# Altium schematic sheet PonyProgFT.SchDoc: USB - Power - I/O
size A3; Author: Claudio Lanconelli; CompanyName: Eurek srl; DrawnBy: Claudio Lanconelli; Organization: Eurek srl; DocumentNumber: 1; SheetNumber: 1; SheetTotal: 1
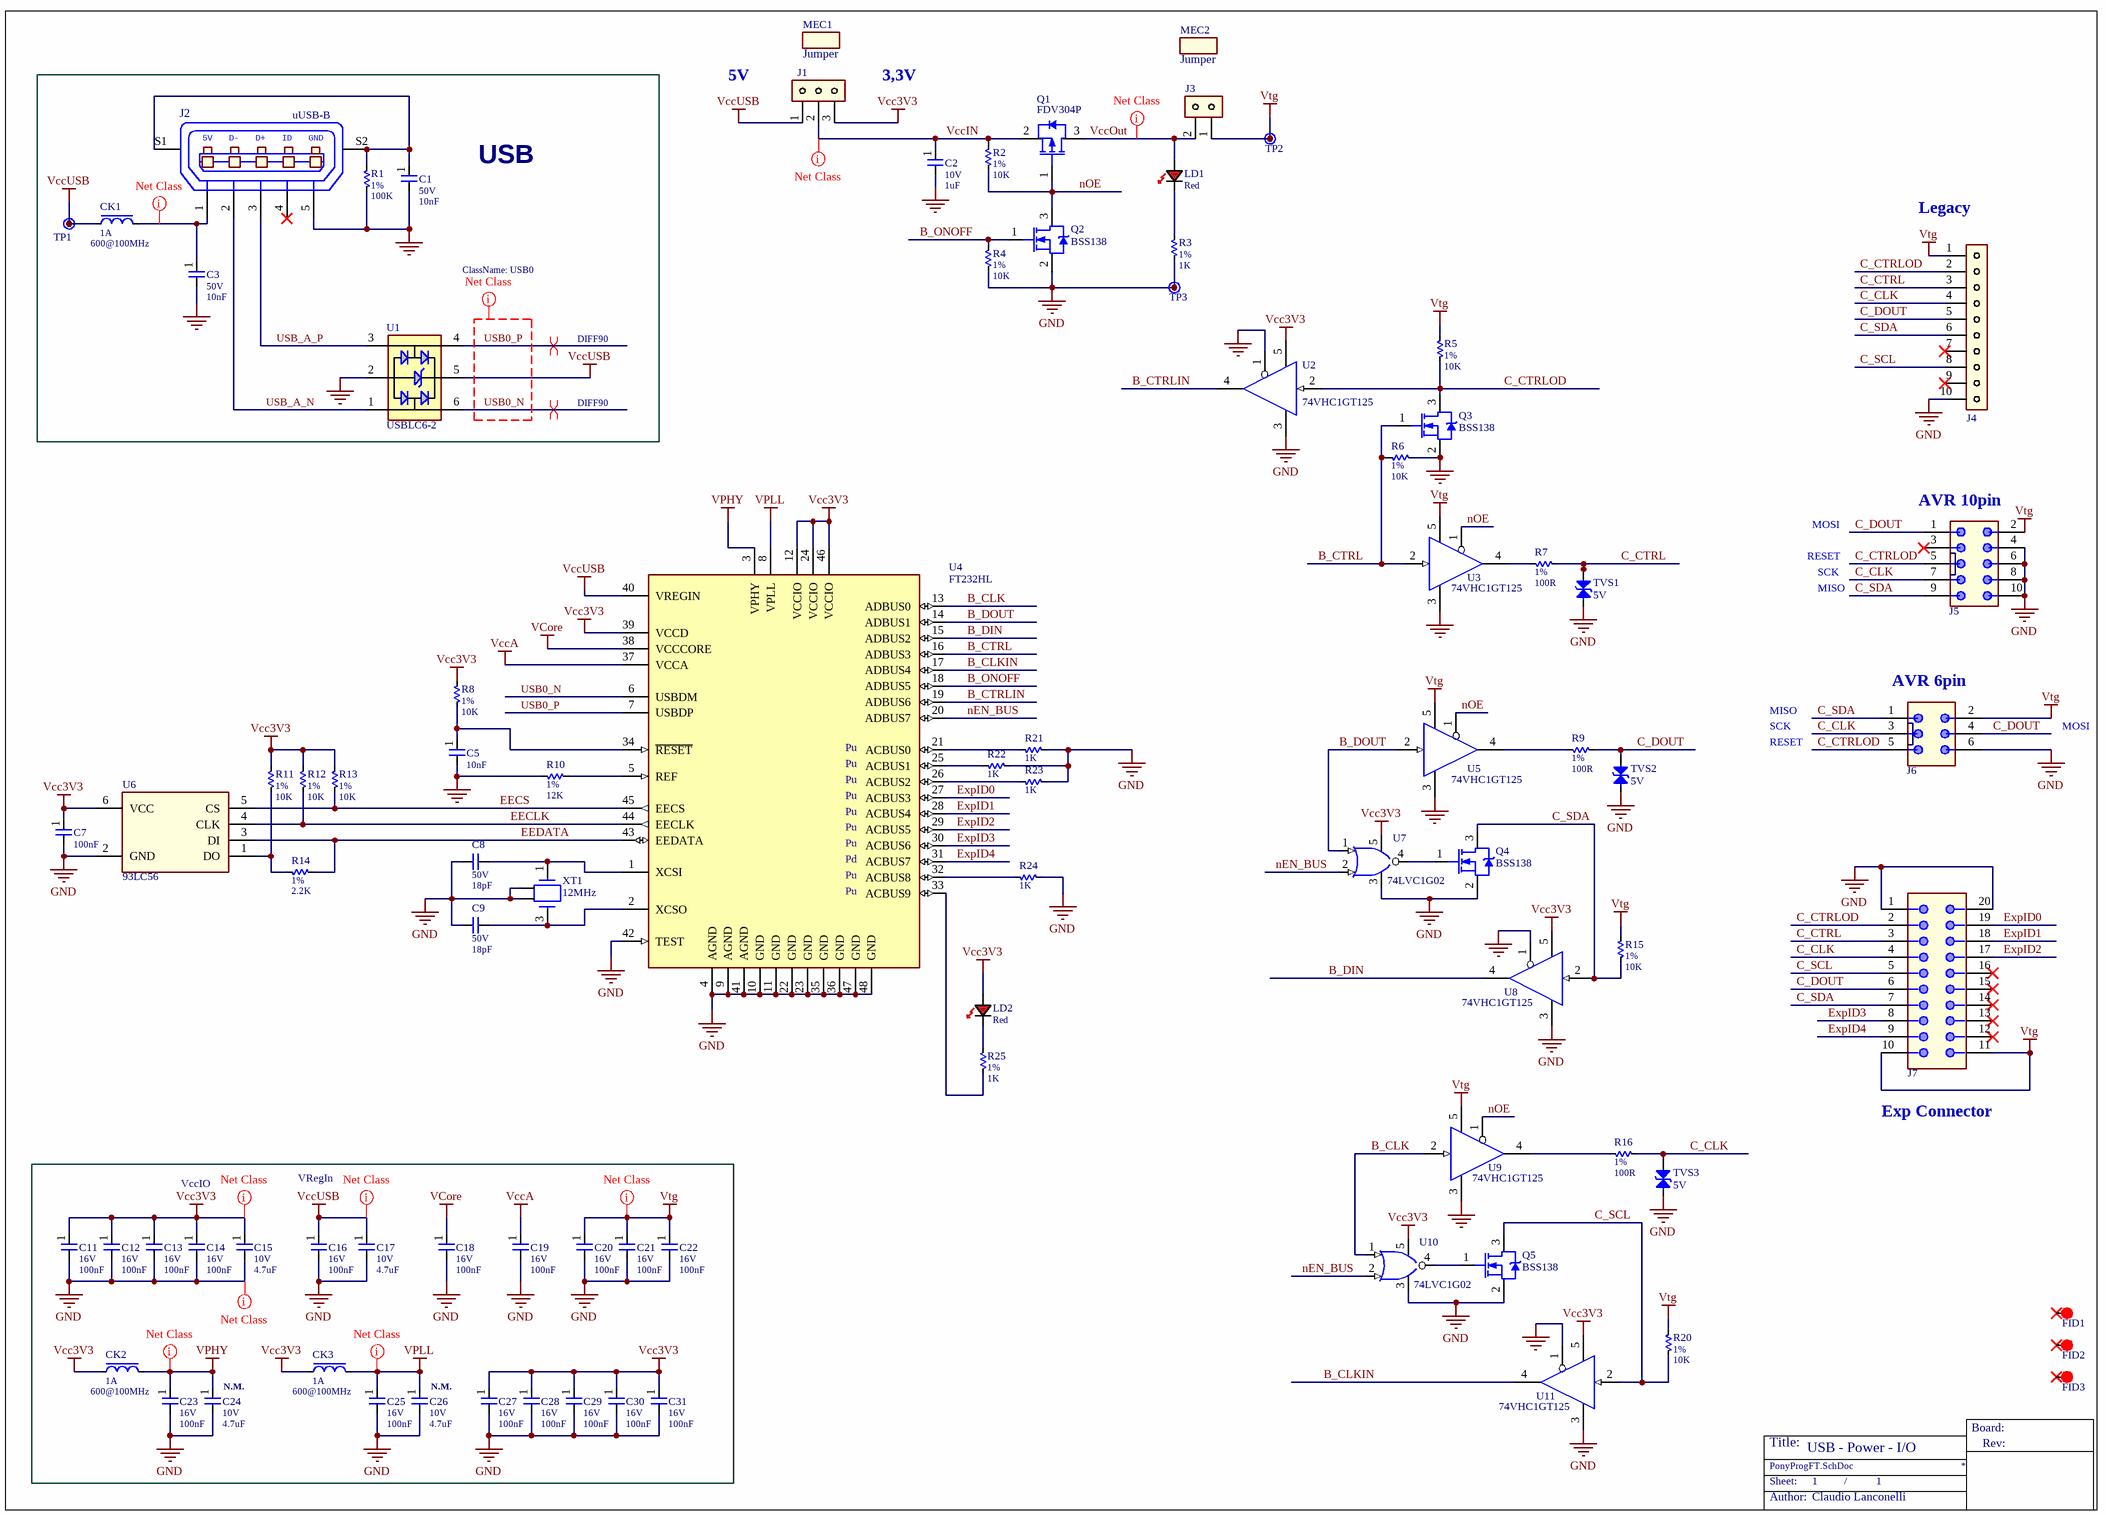
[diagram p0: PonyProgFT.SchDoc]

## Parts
C1  value 10nF  Voltage: 50V  [C0805_M]  (hidden comment: 10nF/50V/0805/10%)
C2  value 1uF  Voltage: 10V  [C0603_M]  (hidden comment: 1uF/10V/0603/10%)
C3  value 10nF  Voltage: 50V  [C0805_M]  (hidden comment: 10nF/50V/0805/10%)
C5  value 10nF  [C0402_H]  (hidden comment: 10nF/25V/0402/10%)
C7  value 100nF  [C0402_H]  (hidden comment: 100nF/16V/0402/10%)
C8  value 18pF  Voltage: 50V  [C0603_M]  (hidden comment: 18pF/50V/0603/5%)
C9  value 18pF  Voltage: 50V  [C0603_M]  (hidden comment: 18pF/50V/0603/5%)
C11  value 100nF  Voltage: 16V  [C0402_H]  (hidden comment: 100nF/16V/0402/10%)
C12  value 100nF  Voltage: 16V  [C0402_H]  (hidden comment: 100nF/16V/0402/10%)
C13  value 100nF  Voltage: 16V  [C0402_H]  (hidden comment: 100nF/16V/0402/10%)
C14  value 100nF  Voltage: 16V  [C0402_H]  (hidden comment: 100nF/16V/0402/10%)
C15  value 4.7uF  Voltage: 10V  [C0603_H]  (hidden comment: 4.7uF/10V/0603/10%)
C16  value 100nF  Voltage: 16V  [C0402_H]  (hidden comment: 100nF/16V/0402/10%)
C17  value 4.7uF  Voltage: 10V  [C0603_H]  (hidden comment: 4.7uF/10V/0603/10%)
C18  value 100nF  Voltage: 16V  [C0402_H]  (hidden comment: 100nF/16V/0402/10%)
C19  value 100nF  Voltage: 16V  [C0402_H]  (hidden comment: 100nF/16V/0402/10%)
C20  value 100nF  Voltage: 16V  [C0402_H]  (hidden comment: 100nF/16V/0402/10%)
C21  value 100nF  Voltage: 16V  [C0402_H]  (hidden comment: 100nF/16V/0402/10%)
C22  value 100nF  Voltage: 16V  [C0402_H]  (hidden comment: 100nF/16V/0402/10%)
C23  value 100nF  Voltage: 16V  [C0402_H]  (hidden comment: 100nF/16V/0402/10%)
C24  value 4.7uF  Populated: N.M.  Voltage: 10V  [C0603_H]  (hidden comment: 4.7uF/10V/0603/10%)
C25  value 100nF  Voltage: 16V  [C0402_H]  (hidden comment: 100nF/16V/0402/10%)
C26  value 4.7uF  Populated: N.M.  Voltage: 10V  [C0603_H]  (hidden comment: 4.7uF/10V/0603/10%)
C27  value 100nF  Voltage: 16V  [C0402_H]  (hidden comment: 100nF/16V/0402/10%)
C28  value 100nF  Voltage: 16V  [C0402_H]  (hidden comment: 100nF/16V/0402/10%)
C29  value 100nF  Voltage: 16V  [C0402_H]  (hidden comment: 100nF/16V/0402/10%)
C30  value 100nF  Voltage: 16V  [C0402_H]  (hidden comment: 100nF/16V/0402/10%)
C31  value 100nF  Voltage: 16V  [C0402_H]  (hidden comment: 100nF/16V/0402/10%)
CK1  value 600@100MHz  RatedCurrent: 1A  [C0603_M]  (hidden comment: 600@100MHz/1A/0603)
CK2  value 600@100MHz  RatedCurrent: 1A  [C0603_M]  (hidden comment: 600@100MHz/1A/0603)
CK3  value 600@100MHz  RatedCurrent: 1A  [C0603_M]  (hidden comment: 600@100MHz/1A/0603)
FID1  Fiducial  [FID_1MM]  (value not drawn)
FID2  Fiducial  [FID_1MM]  (value not drawn)
FID3  Fiducial  [FID_1MM]  (value not drawn)
J1  61300311121  [CON_WE_61300311121]  (value not drawn)
J2  Type: uUSB-B  [CON_FCI_10118192]  (hidden comment: 10118192-0001LF)
J3  61300211121  [CON_WE_61300211121]  (value not drawn)
J4  75915-310LF  [CON_FCI_75915-310LF]  (value not drawn)
J5  61201021621  [CON_WE_61201021621]  (value not drawn)
J6  61200621621  [CON_WE_61200621621]  (value not drawn)
J7  10056847-101LF  [CON_FCI_10056847-101LF]  (value not drawn)
LD1  Red  [LED_WL-SMCW_1206]
LD2  Red  [LED_WL-SMCW_1206]
MEC1  Jumper  (mechanical)
MEC2  Jumper  (mechanical)
Q1  FDV304P  [SOT23-3_H]
Q2  BSS138  [SOT23-3_H]
Q3  BSS138  [SOT23-3_H]
Q4  BSS138  [SOT23-3_H]
Q5  BSS138  [SOT23-3_H]
R1  value 100K  Tolerance: 1%  [C0603_M]  (hidden comment: 100K/1%/0603)
R2  value 10K  Tolerance: 1%  [C0603_M]  (hidden comment: 10K/1%/0603)
R3  value 1K  Tolerance: 1%  [C0603_M]  (hidden comment: 1K/1%/0603)
R4  value 10K  Tolerance: 1%  [C0603_M]  (hidden comment: 10K/1%/0603)
R5  value 10K  Tolerance: 1%  [C0603_M]  (hidden comment: 10K/1%/0603)
R6  value 10K  Tolerance: 1%  [C0603_M]  (hidden comment: 10K/1%/0603)
R7  value 100R  Tolerance: 1%  [C0603_M]  (hidden comment: 100R/1%/0603)
R8  value 10K  Tolerance: 1%  [C0603_M]  (hidden comment: 10K/1%/0603)
R9  value 100R  Tolerance: 1%  [C0603_M]  (hidden comment: 100R/1%/0603)
R10  value 12K  Tolerance: 1%  [C0603_M]  (hidden comment: 12K/1%/0603)
R11  value 10K  Tolerance: 1%  [C0603_M]  (hidden comment: 10K/1%/0603)
R12  value 10K  Tolerance: 1%  [C0603_M]  (hidden comment: 10K/1%/0603)
R13  value 10K  Tolerance: 1%  [C0603_M]  (hidden comment: 10K/1%/0603)
R14  value 2.2K  Tolerance: 1%  [C0402_H]  (hidden comment: 2.2K/1%/0402)
R15  value 10K  Tolerance: 1%  [C0603_M]  (hidden comment: 10K/1%/0603)
R16  value 100R  Tolerance: 1%  [C0603_M]  (hidden comment: 100R/1%/0603)
R20  value 10K  Tolerance: 1%  [C0603_M]  (hidden comment: 10K/1%/0603)
R21  value 1K  [C0603_M]  (hidden comment: 1K/1%/0603)
R22  value 1K  [C0603_M]  (hidden comment: 1K/1%/0603)
R23  value 1K  [C0603_M]  (hidden comment: 1K/1%/0603)
R24  value 1K  [C0603_M]  (hidden comment: 1K/1%/0603)
R25  value 1K  Tolerance: 1%  [C0603_M]  (hidden comment: 1K/1%/0603)
TP1  non montare  [TP-1MM]  (value not drawn)  (no BOM)
TP2  non montare  [TP-1MM]  (value not drawn)  (no BOM)
TP3  non montare  [TP-1MM]  (value not drawn)  (no BOM)
TVS1  Voltage: 5V  [C0603_M]  (hidden comment: 82356050560)
TVS2  Voltage: 5V  [C0603_M]  (hidden comment: 82356050560)
TVS3  Voltage: 5V  [C0603_M]  (hidden comment: 82356050560)
U1  Series: USBLC6-2  [SOT-666_M]  (hidden comment: USBLC6-2P6)
U2  Serie: 74VHC1GT125  [TSOP5-ON]  (hidden comment: M74VHC1GT125DT1G)
U3  Serie: 74VHC1GT125  [TSOP5-ON]  (hidden comment: M74VHC1GT125DT1G)
U4  FT232HL  [LQFP48_P50_M-STM]
U5  Serie: 74VHC1GT125  [TSOP5-ON]  (hidden comment: M74VHC1GT125DT1G)
U6  Serie: 93LC56  [SOT23-6_M]  (hidden comment: 93LC56BT-I/OT)
U7  value 74LVC1G02  [SOT23-5_M]  (hidden comment: 74LVC1G02GV,125)
U8  Serie: 74VHC1GT125  [TSOP5-ON]  (hidden comment: M74VHC1GT125DT1G)
U9  Serie: 74VHC1GT125  [TSOP5-ON]  (hidden comment: M74VHC1GT125DT1G)
U10  value 74LVC1G02  [SOT23-5_M]  (hidden comment: 74LVC1G02GV,125)
U11  Serie: 74VHC1GT125  [TSOP5-ON]  (hidden comment: M74VHC1GT125DT1G)
XT1  value 12MHz  [XTAL-NX3225SA]

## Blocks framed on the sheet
USB: C1 C3 CK1 J2 R1 TP1 U1

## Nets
GND: C1.2 C2.2 C3.2 C5.2 C7.2 C8.1 C9.1 C11.2 C12.2 C13.2 C14.2 C15.2 C16.2 C17.2 C18.2 C19.2 C20.2 C21.2 C22.2 C23.2 C24.2 C25.2 C26.2 C27.2 C28.2 C29.2 C30.2 C31.2 J2.5(P5) J4.10 J5.4 J5.6 J5.8 J5.10 J6.6 J7.1 J7.20 Q2.2(S) Q3.2(S) Q4.2(S) Q5.2(S) R1.2 R3.2 R4.2 R6.2 R10.1 R21.1 R22.1 R23.1 R24.1 TP3.1(TP) TVS1.1 TVS2.1 TVS3.1 U1.2 U2.1(~{OE}) U2.3(GND) U3.3(GND) U4.4(AGND) U4.9(AGND) U4.10(GND) U4.11(GND) U4.22(GND) U4.23(GND) U4.35(GND) U4.36(GND) U4.41(AGND) U4.42(TEST) U4.47(GND) U4.48(GND) U5.3(GND) U6.2(GND) U7.3(GND) U8.1(~{OE}) U8.3(GND) U9.3(GND) U10.3(GND) U11.1(~{OE}) U11.3(GND) XT1.2(GND) XT1.4(GND)
Vcc3V3: C7.1 C11.1 C12.1 C13.1 C14.1 C15.1 C27.1 C28.1 C29.1 C30.1 C31.1 CK2.1 CK3.1 J1.3 LD2.A(Anode) R8.2 R11.1 R12.1 R13.1 U2.5(VCC) U4.12(VCCIO) U4.24(VCCIO) U4.39(VCCD) U4.46(VCCIO) U6.6(VCC) U7.5(VCC) U8.5(VCC) U10.5(VCC) U11.5(VCC)
VccA: C19.1 U4.37(VCCA)
VccUSB: C16.1 C17.1 CK1.1 J1.1 TP1.1(TP) U1.5 U4.40(VREGIN)
VCore: C18.1 U4.38(VCCCORE)
VPHY: C23.1 C24.1 CK2.2 U4.3(VPHY)
VPLL: C25.1 C26.1 CK3.2 U4.8(VPLL)
Vtg: C20.1 C21.1 C22.1 J3.1 J4.1 J5.2 J6.2 J7.10 J7.11 R5.1 R15.2 R20.1 TP2.1(TP) U3.5(VCC) U5.5(VCC) U9.5(VCC)
B_CLK: U4.13(ADBUS0) U9.2(A) U10.1(A)
B_CLKIN: U4.17(ADBUS4) U11.4(Y)
B_CTRL: Q3.1(G) R6.1 U3.2(A) U4.16(ADBUS3)
B_CTRLIN: U2.4(Y) U4.19(ADBUS6)
B_DIN: U4.15(ADBUS2) U8.4(Y)
B_DOUT: U4.14(ADBUS1) U5.2(A) U7.1(A)
B_ONOFF: Q2.1(G) R4.1 U4.18(ADBUS5)
C_CLK: J4.4 J5.7 J6.3 J7.4 R16.2 TVS3.2
C_CTRL: J4.3 J7.3 R7.2 TVS1.2
C_CTRLOD: J4.2 J5.5 J6.5 J7.2 Q3.3(D) R5.2 U2.2(A)
C_DOUT: J4.5 J5.1 J6.4 J7.6 R9.2 TVS2.2
C_SCL: J4.8 J7.5 Q5.3(D) R20.2 U11.2(A)
C_SDA: J4.6 J5.9 J6.1 J7.7 Q4.3(D) R15.1 U8.2(A)
EECLK: R12.2 U4.44(EECLK) U6.4(CLK)
EECS: R13.2 U4.45(EECS) U6.5(CS)
EEDATA: R14.2 U4.43(EEDATA) U6.3(DI)
ExpID0: J7.19 U4.27(ACBUS3)
ExpID1: J7.18 U4.28(ACBUS4)
ExpID2: J7.17 U4.29(ACBUS5)
ExpID3: J7.8 U4.30(ACBUS6)
ExpID4: J7.9 U4.31(ACBUS7)
nEN_BUS: U4.20(ADBUS7) U7.2(B) U10.2(B)
nOE: Q1.1(G) Q2.3(D) R2.2 U3.1(~{OE}) U5.1(~{OE}) U9.1(~{OE})
USB0_N: U1.6 U4.6(USBDM)
USB0_P: U1.4 U4.7(USBDP)
USB_A_N: J2.2(P2) U1.1
USB_A_P: J2.3(P3) U1.3
VccIN: C2.1 J1.2 Q1.2(S) R2.1
VccOut: J3.2 LD1.A(Anode) Q1.3(D)
NetC1_1: C1.1 J2.S1(Shell1) J2.S2(Shell2) R1.1
NetC3_1: C3.1 CK1.2 J2.1(P1)
NetC5_1: C5.1 R8.1 U4.34(~{RESET})
NetC8_2: C8.2 U4.1(XCSI) XT1.1
NetC9_2: C9.2 U4.2(XCSO) XT1.3
NetLD1_K: LD1.K(Cathode) R3.1
NetLD2_K: LD2.K(Cathode) R25.2
NetQ4_1: Q4.1(G) U7.4(Y)
NetQ5_1: Q5.1(G) U10.4(Y)
NetR7_1: R7.1 U3.4(Y)
NetR9_1: R9.1 U5.4(Y)
NetR10_2: R10.2 U4.5(REF)
NetR11_2: R11.2 R14.1 U6.1(DO)
NetR16_1: R16.1 U9.4(Y)
NetR21_2: R21.2 U4.21(ACBUS0)
NetR22_2: R22.2 U4.25(ACBUS1)
NetR23_2: R23.2 U4.26(ACBUS2)
NetR24_2: R24.2 U4.32(ACBUS8)
NetR25_1: R25.1 U4.33(ACBUS9)

Not connected (* = marked no-connect by the designer): FID1 1*; FID2 1*; FID3 1*; J2 4(P4)*; J4 7* 9*; J5 3*; J7 12* 13* 14* 15* 16*

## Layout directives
differential pair; net class DIFF90: USB0_N, USB0_P
net class USB0: USB0_N, USB0_P
net class NETPWR: GND, NetC3_1, Vcc3V3, VccIN, VccOut, VccUSB, VPHY, VPLL, Vtg

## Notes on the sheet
- 5V
- 3,3V
- (near J4) Legacy
- (near J5) AVR 10pin
- RESET
- MOSI
- SCK
- MISO
- (near J6) AVR 6pin
- (near U4) Pu
- (near U4) Pd
- (near J7) Exp Connector
- VccIO
- VRegIn

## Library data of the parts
C1 C3 = CX7R10N50V10%0805_CL: Chip Ceramic Capacitor X7R 0805 10nF 50V 10%; Manufacturer: Samsung Electro-Mechanics; Sep: /; Prefix: CX7R; Man_PN: CL21B103KBCNNNC; TemperatureRange: -55°C ~ 125°C
C2 = CX5R1U10V10%0603_GRM: Chip Ceramic Capacitor X5R 0603 1uF 10V 10%; Manufacturer: Murata Electronics North America; Sep: /; Prefix: CX5R; Man_PN: GRM188R61A105KA61D; TemperatureRange: -55 to +85 C; Brand: Murata Electronics
C5 = CX7R10N25V10%0402_GRM: Chip Ceramic Capacitor X7R 0402 10nF 25V 10%; Manufacturer: Murata Electronics North America; Sep: /; Prefix: CX7R; Man_PN: GRM155R71E103KA01D; TemperatureRange: - 55 C to + 125 C; Brand: Murata Electronics
C7 C11-C14 C16 C18-C23 C25 C27-C31 = CX7R100N16V10%0402_GRM: Chip Ceramic Capacitor X7R 0402 100nF 16V 10%; Manufacturer: Murata Electronics North America; Sep: /; Prefix: CX7R; Man_PN: GRM155R71C104KA88D; Capacitance: 0.1µF; TemperatureRange: -55°C ~ 125°C; Serie: GRM
C8 C9 = CCOG18P50V5%0603_KEMET: Chip Ceramic Capacitor C0G 0603 18pF 50V 5%; Manufacturer: Kemet; Sep: /; Prefix: CCOG; TemperatureRange: -55°C ~ 125°C; Man_PN: C0603C180J5GACTU
C15 C17 C24 C26 = CX5R4.7U10V10%0603_TDK: Chip Ceramic Capacitor X5R 0603 4.7uF 10V 10%; Manufacturer: TDK Corporation; Sep: /; Prefix: CX5R; Man_PN: CGB3B1X5R1A475K055AC; Capacitance: 4.7µF; TemperatureRange: -55 to 85°C; Gamma Prodotti: Serie CGB; Imballaggio: Nastro
CK1-CK3 = FCB600Z1A0603MPZ: Ferrite Chip Beads SMD 0603 600@100MHz 1A; Manufacturer: TDK Corporation; Sep: /; Prefix: FCB; Man_PN: MPZ1608S601ATA00; TemperatureRange: - 55 C to + 125 C; Tolerance: 25 %; Brand: TDK
FID1-FID3 = FID: Fiducial (non montare); Sep: /; Populated: N.M.
J1 = CON_WE_61300311121: THT Vertical Pin Header Male WR-PHD, Pitch 2.54 mm, Single Row, 3 pins; Manufacturer: WE; Sep: /; Prefix: CON; Voltage: 250VAC; TemperatureRange: -40 to 105 degC; RatedCurrent: 3A
J2 = CON_FCI_10118192-0001LF: Micro-USB Type-B, right-angle, horizontal receptacle; Manufacturer: FCI; Sep: /; Connector Type: USB - micro B; Number of Contacts: 5; USB Standard: USB 2.0; Livello di Corrente: 1; Resistenza Contatto: 40; Tensione Nominale V AC: 100; Tipo Terminazione Contatto: A Saldare; RatedCurrent: 1.8 A; Mounting Angle: Right; TemperatureRange: - 55 C to + 85 C; Insulation Resistance: 1000 MOhms
J3 = CON_WE_61300211121: THT Vertical Pin Header Male WR-PHD, Pitch 2.54 mm, Single Row, 2 pins; Manufacturer: WE; Sep: /; Prefix: CON; Voltage: 250VAC; TemperatureRange: -40 to 105 degC; RatedCurrent: 3A
J4 = CON_FCI_75915-310LF: CONN RCPT 10POS 0.1 GOLD PCB; Manufacturer: FCI; Sep: /
J5 = CON_WE_61201021621: Male Box Header WR-BHD, THT, Vertical, pitch 2.54 mm, 10 pins; Manufacturer: WE; Sep: /; Prefix: CON; Voltage: 250Vac; TemperatureRange: -40 to 125 degC
J6 = CON_WE_61200621621: Male Box Header WR-BHD, THT, Vertical, pitch 2.54 mm, 6 pins; Manufacturer: WE; Sep: /; Prefix: CON; Voltage: 250V; TemperatureRange: -40 to +125; RatedCurrent: 3 A
J7 = CON_FCI_10056847-101LF: Connector edge dual female 20 pos, 0.8pitch; Manufacturer: Amphenol ICC (FCI); Sep: /; Prefix: CON
LD1 LD2 = LED_WE_150120RS75000: Chip LED SMD WL-SMCW, size 1206, Red, 2V, 140 deg, 150 mcd; Manufacturer: Wurth Electronics Inc.; Sep: /; Prefix: CLED; TemperatureRange: -40 up to +85 °C
MEC1 MEC2 = MEC___: Jumper with pullback, 2.54mm pitch, black; Manufacturer: WE; Tmp: 609002115121; Sep: /; Prefix: MEC; Serie: WR-PHD; RatedCurrent: 3A
Q1 = IC_FDV304P: IC MOSFET P-CH 25V 460mA SOT-23; Manufacturer: On Semiconductor; Sep: /; TemperatureRange: -55°C ~ 150°C (TJ)
Q2-Q5 = IC_BSS138: MOSFET N-CH 50V 0.22A SOT-23; Manufacturer: Fairchild Semiconductor; Sep: /; Prefix: IC; RatedCurrent: 220mA; Rated_Power: 360mW; TemperatureRange: - 55 C to 150 C
R1 = CRES100K1%100P0603T_CRCW: Chip Resistor 0603 100K 1% 100ppm; Manufacturer: Vishay Dale; Sep: /; Prefix: CRES; Watt: 1/10; ppm: 100; Voltage: 75V; Man_PN: CRCW0603100KFKEA; Temperature Coefficient: ±100ppm/°C; TemperatureRange: -55°C ~ 155°C
R2 R4-R6 R8 R11-R13 R15 R20 = CRES10K1%100P0603T_CRCW: Chip Resistor 0603 10K 1% 100ppm; Manufacturer: Vishay Dale; Sep: /; Prefix: CRES; Watt: 1/10; ppm: 100; Voltage: 75V; Man_PN: CRCW060310K0FKEA; Temperature Coefficient: ±100ppm/°C; TemperatureRange: -55°C ~ 155°C; TemperatureRange: - 55 C to + 155 C; RatedPower: 100 mW; Brand: Vishay / Dale
R3 R21-R25 = CRES1K1%100P0603T_CRCW: Chip Resistor 0603 1K 1% 100ppm; Manufacturer: Vishay Dale; Sep: /; Prefix: CRES; Watt: 1/10; ppm: 100; Voltage: 75V; Man_PN: CRCW06031K00FKEA; Temperature Coefficient: ±100ppm/°C; TemperatureRange: -55°C ~ 155°C; RatedPower: 100 mW; Brand: Vishay / Dale
R7 R9 R16 = CRES100R1%100P0603T_CRCW: Chip Resistor 0603 100R 1% 100ppm; Manufacturer: Vishay Dale; Sep: /; Prefix: CRES; Watt: 1/10; ppm: 100; Voltage: 75V; Man_PN: CRCW0603100RFKEA; Temperature Coefficient: ±100ppm/°C; TemperatureRange: -55°C ~ 155°C; TemperatureRange: - 55 C to + 155 C; RatedPower: 100 mW; Brand: Vishay / Dale
R10 = CRES12K1%100P0603T_CRCW: Chip Resistor 0603 12K 1% 100ppm; Manufacturer: Vishay; Sep: /; Prefix: CRES; Watt: 1/10; ppm: 100; Voltage: 75V; TemperatureRange: -55°C ~ 155°C; Man_PN: CRCW060312K0FKEAC; Serie: CRCW
R14 = CRES2.2K1%100P0402U_CRCW: Chip Resistor 0402 2.2K 1% 100ppm; Manufacturer: Vishay Dale; Sep: /; Prefix: CRES; Watt: 1/16; ppm: 100; Voltage: 50V; Man_PN: CRCW04022K20FKED; Temperature Coefficient: ±100ppm/°C; TemperatureRange: -55°C ~ 155°C; TemperatureRange: - 55 C to + 155 C; RatedPower: 63 mW; Brand: Vishay / Dale
TP1-TP3 = TP_TPH-1MM: Test Point, D=1mm (Foro 0.5mm), non montare; Value: TP d=1mm (foro 0.5mm); Populated: N.M.; Sep: /; Prefix: TP
TVS1-TVS3 = TVSP_WE-82356050560: Chip ESD suppressor bidirectional 5V 0603; Manufacturer: WE; Sep: /; Prefix: TVSP
U1 = IC_USBLC6-2P6: TVS 2 line, Low cap, 5V, SOT666; Manufacturer: STMicroelectronics; Sep: /; Prefix: IC; Voltage - Reverse Standoff (Typ): 5.25V; Voltage - Breakdown (Min): 6V; Voltage - Clamping (Max) @ Ipp: 17V; Current - Peak Pulse (10/1000µs): 5A (8/20µs); Power Line Protection: Yes; TemperatureRange: -40°C ~ 125°C (TJ); No. di Pin: 6; Tipo di Diodo: Unidirezionale, TVS; Breakdown Voltage: 6 V; Clamping Voltage: 17 V; Number of Channels: 2 Channel; Cd - Diode Capacitance: 3.5 pF
U2 U3 U5 U8 U9 U11 = IC_M74VHC1GT125DT: IC BUFFER NON-INVERT 5.5V 5-TSOP; Manufacturer: ON Semiconductor; Sep: /; TemperatureRange: -55°C ~ 125°C (TA)
U4 = IC_FT232HL: IC HS USB TO UART/FIFO 48LQFP; Manufacturer: FTDI; Sep: /; TemperatureRange: -40°C ~ 85°C
U6 = IC_93LC56BT-I/OT: IC EEPROM 2K SPI 2MHz SOT23-6; Manufacturer: Microchip; Sep: /; TemperatureRange: -40°C ~ 85°C (TA)
U7 U10 = IC_74LVC1G02GV: IC GATE NOR 1CH 2-INP 5-TSOP; Manufacturer: NXP Semiconductors; Sep: /; TemperatureRange: -40°C to 125°C; Serie: LVC
XT1 = XTAL_NX3225SA-12MHZ-STD-CSR-6: Xtal SMD 12MHz 8pF 25ppm (-40 to 85); Manufacturer: NDK; Sep: /; TemperatureRange: -40°C to 85°C; ESR: 100 Ohm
